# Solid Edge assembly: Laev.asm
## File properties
Author: Egon 815
Template: Normal.asm
Last saved by: egono
Revision: 74
Application: Solid Edge
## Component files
Jubin.psm
SuurKahur.par
ljeKahur_mir2.par
JuhtimisKeskus.par
Korsten.par
Radar.par
Raketid.par
Raketikorpus.par
LaevaKere12.par
SuurKruvi.par
Mootor.par
Dekk1.par
Dekk2.par
ljeKahur.par
ris.par
AlusJoonised.par
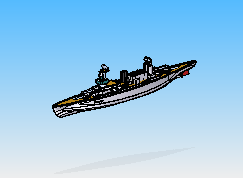
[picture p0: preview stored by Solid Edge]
